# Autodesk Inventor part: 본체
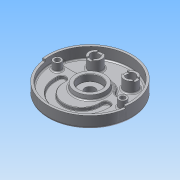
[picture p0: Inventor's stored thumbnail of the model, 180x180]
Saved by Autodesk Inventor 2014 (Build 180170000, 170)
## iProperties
Created: 2015-06
Part Number: 본체
Material: 알루미늄 6061
Document SubType Name: Modeling
Designer: Administrator
Density: 2.71 g/cm^3
Appearance: 알루미늄 - 평지
Mass: 1115.25 g
Surface Area: 1045.8 cm^2
Volume: 411.532 cm^3
Author: Administrator
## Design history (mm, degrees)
sketch "스케치1"
  geometry: C1 r 95 at (0, 0); 1 further point
  constraints: 1 centre point, 1 coincident
  dimensions: "d0" = 190 diameter of C1
extrude "돌출1" new body sketch "스케치1" distance "d1" = 32; taper "d2" = 0 deg
hole "구멍1" diameter "d5" = 180; stored, may be unused: countersink angle "d9" = 90 deg, drill point angle "d11" = 0 deg; dims "d3" = 10, "d4" = 10, "d6" = 6, "d7" = 4, "d8" = 2, "d10" = 25
sketch "스케치2"
  geometry: L1 (-95, 0)-(95, 0); L2 (0, 0)-(-94.075, -13.221); L3 (0, 0)-(94.075, -13.221); C1 r 90 at (0, 0) reference; A1 r 95 centre (0, 0) between (-95, 0) and (95, 0) reference
  constraints: 6 end point, 4 point on circle, 1 coincident, 1 horizontal, 1 midpoint
  dimensions: "d12" = 8 deg angle of L2 L1; "d13" = 8 deg angle of L3 L1
extrude "돌출2" cut sketch "스케치2" distance "d14" = 5; taper "d15" = 0 deg
sketch "스케치3"
  geometry: C1 r 90 at (0, 0) reference; C2 r 42 at (0, 0)
  constraints: 1 centre point, 1 coincident
  dimensions: "d16" = 84 diameter of C2
extrude "돌출3" join sketch "스케치3" distance "d17" = 7; taper "d18" = 0 deg
sketch "스케치4"
  geometry: C1 r 42 at (0, 0) reference; C2 r 35 at (0, 0)
  constraints: 1 centre point, 1 coincident
  dimensions: "d19" = 70 diameter of C2
extrude "돌출4" join sketch "스케치4" distance "d20" = 10; taper "d21" = -10 deg
hole "구멍2" diameter "d24" = 23; stored, may be unused: countersink angle "d28" = 90 deg, drill point angle "d30" = 0 deg; dims "d25" = 6, "d26" = 50, "d27" = 15, "d29" = 23, "d111" = 10, "d112" = 10
sketch "스케치5"
  geometry: C1 r 95 at (0, 0) reference; C2 r 26 at (0, 0)
  constraints: 1 centre point, 1 coincident
  dimensions: "d31" = 52 diameter of C2
extrude "돌출5" join sketch "스케치5" distance "d32" = 12; taper "d33" = -15 deg
sketch "스케치6"
  geometry: C1 r 42 at (0, 0) reference; C2 r 15 at (-40, 52); C3 r 15 at (40, 52)
  constraints: 2 centre point, 1 equal radius, 1 horizontal alignment
  dimensions: "d35" = 30 diameter of C2; "d36" = 40 horizontal distance of C2.centre C1.centre; "d37" = 40 horizontal distance of C3.centre C1.centre; "d38" = 52 vertical distance of C3.centre C1.centre
extrude "돌출6" join sketch "스케치6" stored distance "d39" = 11.5; taper "d40" = 0 deg
hole "구멍3" diameter "d43" = 20; stored, may be unused: countersink angle "d47" = 90 deg, drill point angle "d49" = 0 deg; dims "d41" = 10, "d42" = 10, "d44" = 6, "d45" = 50, "d46" = 15, "d48" = 23
hole "구멍4" diameter "d52" = 20; stored, may be unused: countersink angle "d56" = 90 deg, drill point angle "d58" = 0 deg; dims "d50" = 10, "d51" = 10, "d53" = 6, "d54" = 50, "d55" = 15, "d57" = 23
sketch "스케치7"
  geometry: L1 (-6, 13.748)-(-6, 8); L2 (-6, -8)-(-6, -13.748); L3 (6, -13.748)-(6, -8); L4 (6, 8)-(6, 13.748); A1 r 10 centre (0, 0) between (-6, 8) and (-6, -8) reference; A2 r 15 centre (0, 0) between (-6, 13.748) and (-6, -13.748) reference; 1 further point
  constraints: 8 end point, 8 point on circle, 6 parallel, 2 vertical
  dimensions: "d60" = 12 distance between parallel lines of L4 L1; "d61" = 12 distance between parallel lines of L3 L2
extrude "돌출7" cut sketch "스케치7" distance "d62" = 3; taper "d63" = 0 deg
sketch "스케치8"
  geometry: L1 (-13.748, 6)-(-8, 6); L2 (8, 6)-(13.748, 6); L3 (-13.748, -6)-(-8, -6); L4 (8, -6)-(13.748, -6); A1 r 10 centre (0, 0) between (-8, 6) and (8, 6) reference; A2 r 15 centre (0, 0) between (-13.748, 6) and (13.748, 6) reference; 1 further point
  constraints: 8 end point, 8 point on circle, 6 parallel, 2 horizontal
  dimensions: "d65" = 12 distance between parallel lines of L3 L1; "d66" = 12 distance between parallel lines of L4 L2
extrude "돌출8" cut sketch "스케치8" distance "d67" = 3; taper "d68" = 0 deg
sketch "스케치9"
  geometry: L1 (-90, 0)-(90, 0); L2 (-88.566, 16)-(-38.833, 16); L3 (38.833, 16)-(88.566, 16); A1 r 42 centre (0, 0) between (-38.833, 16) and (38.833, 16) reference; A2 r 90 centre (0, 0) between (-90, 0) and (-88.566, 16) reference; 1 further point
  constraints: 6 end point, 6 point on circle, 2 parallel, 1 coincident, 1 horizontal, 1 midpoint
  dimensions: "d70" = 16 distance between parallel lines of L1 L2; "d71" = 16 distance between parallel lines of L1 L3
extrude "돌출9" join sketch "스케치9" distance "d72" = 7; taper "d73" = 0 deg
sketch "스케치10"
  geometry: C1 r 35 at (0, 0) reference; C2 r 9 at (-74, 0); C3 r 9 at (74, 0)
  constraints: 2 centre point, 2 horizontal alignment
  dimensions: "d74" = 74 distance of C1.centre C2.centre; "d75" = 74 distance of C3.centre C1.centre; "d76" = 18 diameter of C2; "d77" = 18 diameter of C3
extrude "돌출10" join sketch "스케치10" stored distance "d78" = 7; taper "d79" = 0 deg
sketch "스케치11"
  geometry: C1 r 9 at (-74, 0) reference; C2 r 9 at (74, 0) reference; 2 further points
  constraints: 2 coincident
hole "구멍5" sketch "스케치11" at (-74, 0), (74, 0) diameter "d80" = 11; stored, may be unused: countersink angle "d84" = 90 deg, drill point angle "d86" = 0 deg; dims "d81" = 6, "d82" = 18, "d83" = 11, "d85" = 23
sketch "스케치12"
  geometry: L1 (88.566, 16)-(38.833, 16) reference; L2 (-40.21, 0)-(36.332, 0); L3 (-59, -19)-(59, -19); L4 (-58.788, -14)-(58.788, -14); L5 (-59, -19)-(-59, -14); L6 (-41, -19)-(-41, -14); L7 (41, -19)-(41, -14); L8 (59, -19)-(59, -14); L9 (-50, -19)-(-50, -14); A1 r 59 centre (0, -19) between (-59, -19) and (59, -19); A2 r 41 centre (0, -19) between (-41, -19) and (41, -19); A3 r 9 centre (-50, -14) between (-41, -14) and (-59, -14); A4 r 9 centre (50, -14) between (59, -14) and (41, -14); 4 further points
  constraints: 16 end point, 8 point on circle, 7 parallel, 7 point on line, 5 coincident, 4 centre point, 4 tangent, 1 midpoint, 1 perpendicular, 1 vertical alignment
  dimensions: "d90" = 19 distance from line of point (0, -19) L2; "d91" = 59 radius of A1; "d94" = 5 distance between parallel lines of L3 L4; "d95" = 41 radius of A2; "d97" = 18 diameter of A3; "d99" = 18 diameter of A4; "d102" = 35 distance from line of L9.start L1; "d103" = 0.21225 distance from line of L4.end L8; "d104" = 22.6682 distance from line of L2.end L8; "d105" = 99.21034 distance from line of L2.start L8; "d106" = 117.78775 distance from line of L4.start L8
extrude "돌출11" cut sketch "스케치12" distance "d100" = 7; taper "d101" = 0 deg
sketch "스케치13"
  geometry: C1 r 95 at (0, 0) reference; C2 r 74 at (0, 0); C3 r 68 at (0, 0)
  constraints: 2 centre point, 2 coincident, 1 other
  dimensions: "d107" = 148 diameter of C2; "d108" = 136 diameter of C3
feature "엠보싱1" sketch "스케치13" dims "d109" = 0.5, "d110" = 0
hole "구멍6" diameter "d115" = 23; stored, may be unused: countersink angle "d119" = 90 deg, drill point angle "d121" = 0 deg; dims "d113" = 10, "d114" = 10, "d116" = 6, "d117" = 18, "d118" = 11, "d120" = 23
fillet "모깎기1" dims "d122" = 10
fillet "모깎기2" dims "d123" = 3
fillet "모깎기3" dims "d124" = 3
fillet "모깎기4" dims "d125" = 1
fillet "모깎기5" dims "d126" = 3
fillet "모깎기6" dims "d127" = 3
fillet "모깎기7" dims "d128" = 0.3
chamfer "모따기1" distance "d129" = 1; stored, may be unused: second distance "d130" = 2, angle "d131" = 45 deg
fillet "모깎기8" dims "d132" = 5
node "솔리드1"
other parameters: "d59" = 12, "d64" = 12, "d69" = 16, "d92" = 41, "d93" = 5
